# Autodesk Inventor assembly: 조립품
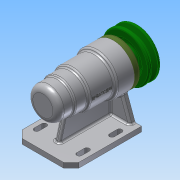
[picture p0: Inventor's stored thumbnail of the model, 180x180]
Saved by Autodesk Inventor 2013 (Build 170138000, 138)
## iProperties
Created: 2017-09
Part Number: 조립품
Document SubType Name: Assembly
Designer: user
Author: user
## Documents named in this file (12)
- C:\Users\user\Desktop\새 폴더\조립품.iam
- C:\Users\user\Desktop\새 폴더\본체.ipt
- C:\Users\user\Desktop\새 폴더\V벨트풀리.ipt
- C:\Users\user\Desktop\새 폴더\멈춤나사 M3x8.ipt
- C:\Users\user\Desktop\새 폴더\베어링 6004.ipt
- C:\Users\user\Desktop\새 폴더\베어링 51202.ipt
- C:\Users\user\Desktop\새 폴더\볼트 M4 x 12.ipt
- C:\Users\user\Desktop\새 폴더\어댑터슬리브.ipt
- C:\Users\user\Desktop\새 폴더\오일 실 20x35x7.ipt
- C:\Users\user\Desktop\새 폴더\축.ipt
- C:\Users\user\Desktop\새 폴더\커버.ipt
- C:\Users\user\Desktop\새 폴더\키 5 x 5 x 16.ipt
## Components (1 placed, 1 different names)
1. V벨트풀리:1
